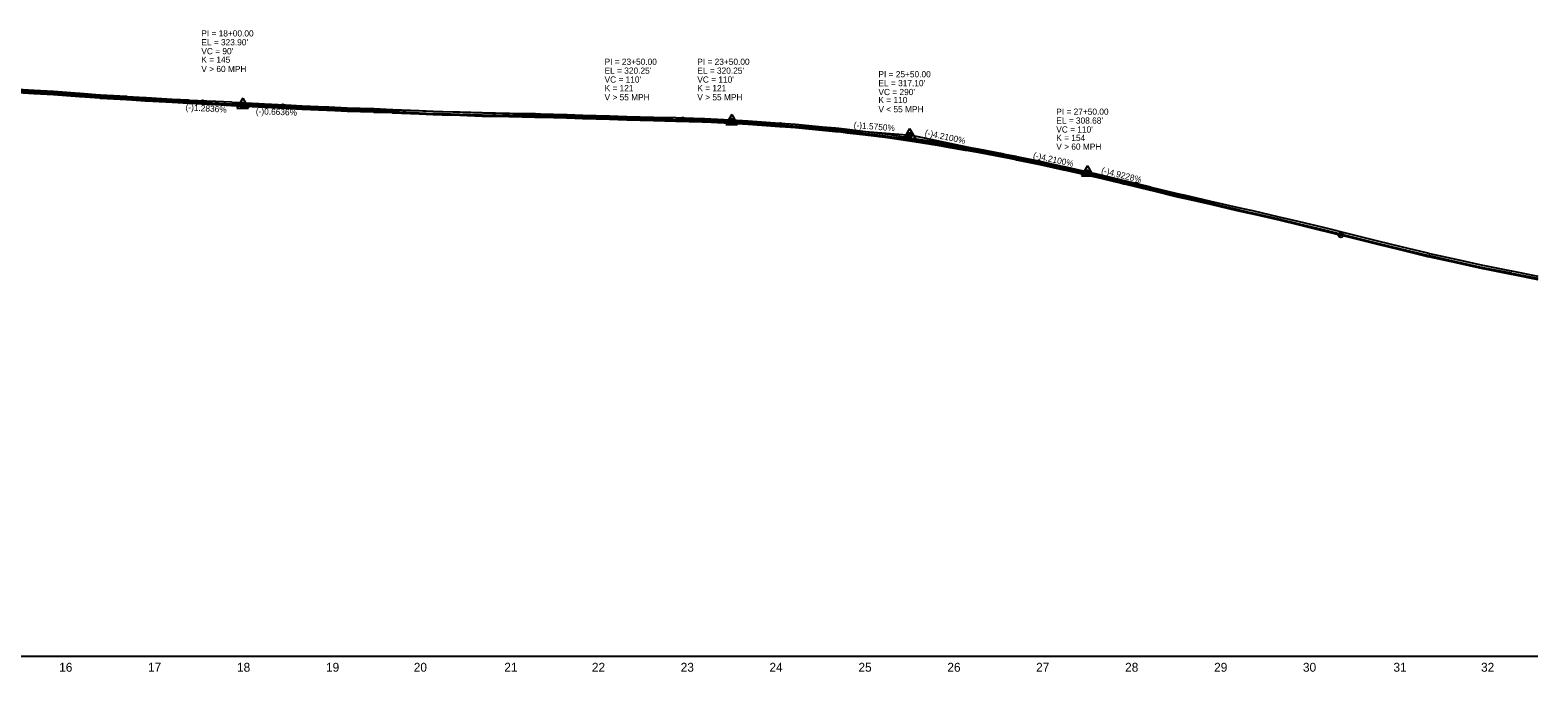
# Model space of a CAD drawing. Extents: x 2111382 to 2119088, y 667477 to 672158.
# Drawn here: x 2113288 to 2114983, y 670803 to 671524 of the extents above; entities that cross this region are included whole.
import ezdxf

# ---------------------------------------------------------------- set-up
doc = ezdxf.new("R2010")
doc.units = 0
for name, color, linetype in [('Exist Profile Cell', 7, 'Continuous'), ('Exist Vertical Profile Ground Line', 7, 'Continuous'), ('Exist Vertical Profile Horizontal Axis Label Major', 7, 'Continuous'), ('Prop PFL VPI Symbol CELL', 7, 'Continuous'), ('Prop Vertical Profile Curve Label', 7, 'Continuous'), ('Prop Vertical Profile Grade', 7, 'Continuous'), ('Prop Vertical Profile Grade Label', 7, 'Continuous'), ('Prop VPI Label', 7, 'Continuous'), ('Scratch_Level_2', 7, 'Continuous'), ('Scratch_Level_3', 7, 'Continuous')]:
    doc.layers.add(name, color=color, linetype=linetype)

msp = doc.modelspace()

# ---------------------------------------------------------------- linework, layer by layer
at = {"layer": 'Exist Profile Cell'}
msp.add_line((2112726.7, 670820.2), (2114983.3, 670820.2), dxfattribs=at)
at = {"layer": 'Exist Vertical Profile Ground Line'}
for points in [[(2113262.2, 671454.5), (2113291.9, 671452.7), (2113292.3, 671452.6), (2113313.9, 671451.3), (2113343.1, 671449.2), (2113343.9, 671449.1), (2113366.1, 671447.5), (2113366.7, 671447.4), (2113395.9, 671445.6), (2113396.7, 671445.6), (2113417, 671444.3), (2113417.5, 671444.3), (2113418.2, 671444.3), (2113447.5, 671442.6), (2113466.1, 671441.5), (2113466.7, 671441.5), (2113495.9, 671440.1), (2113496.7, 671440), (2113514.2, 671439.2), (2113514.6, 671439.2), (2113544.7, 671437.6), (2113551.1, 671437.3), (2113574.5, 671436), (2113574.8, 671436), (2113593.6, 671435), (2113621.3, 671433.9), (2113623.6, 671433.8), (2113644.3, 671432.8), (2113673.8, 671431.8), (2113674.3, 671431.7), (2113674.7, 671431.7), (2113695, 671431), (2113695.5, 671430.9), (2113725.2, 671429.6), (2113740.8, 671428.9), (2113751, 671428.6), (2113770.8, 671428), (2113771.1, 671428), (2113796.1, 671427.2), (2113826.1, 671426.7), (2113826.6, 671426.7), (2113855.3, 671426.1), (2113856.2, 671426.1), (2113861.6, 671426), (2113891, 671425.1), (2113891.6, 671425.1), (2113908.9, 671424.6), (2113909.3, 671424.6), (2113939.2, 671423.6), (2113958.6, 671423), (2113988.6, 671422.2), (2114013.8, 671421.6), (2114043.4, 671420.8), (2114043.9, 671420.8), (2114045.5, 671420.7), (2114046, 671420.7), (2114075.5, 671419.1), (2114075.8, 671419.1), (2114095.3, 671418), (2114125.4, 671415.8), (2114148.4, 671414.2), (2114178.3, 671411.4), (2114193.4, 671410), (2114197.3, 671409.7), (2114206.7, 671408.5), (2114227.3, 671406), (2114251.8, 671403), (2114282, 671398.4), (2114309.9, 671394.1), (2114310.3, 671394), (2114317.8, 671392.7), (2114339.4, 671389), (2114340.3, 671388.8), (2114353.3, 671386.5), (2114382.6, 671380.9), (2114383.2, 671380.8), (2114396.4, 671378.2), (2114397, 671378.1), (2114423.2, 671372.6), (2114450, 671366.7), (2114450.4, 671366.6), (2114480.1, 671360.1), (2114485, 671358.9), (2114485.6, 671358.7), (2114515, 671351.7), (2114517.6, 671351.1), (2114518.3, 671350.9), (2114547.6, 671343.8), (2114548.1, 671343.7), (2114577.5, 671336.5), (2114584.8, 671334.9), (2114585.1, 671334.8), (2114615, 671328), (2114644.8, 671321.1), (2114658.6, 671318), (2114662.2, 671317.2), (2114692.1, 671310.4), (2114713.2, 671305.3), (2114743.3, 671298.2)], [(2114743.3, 671298.2), (2114773, 671290.6), (2114802.9, 671283.1), (2114829.3, 671276.7), (2114859.3, 671269.5), (2114861.3, 671269.1), (2114891.2, 671262.5), (2114921.2, 671255.9), (2114923.4, 671255.4), (2114953.3, 671249.5), (2114953.7, 671249.5), (2114983.3, 671243.6)]]:
    msp.add_lwpolyline(points, dxfattribs=at)
at = {"layer": 'Prop PFL VPI Symbol CELL'}
for p, q in [((2113526.7, 671447.2), (2113520.2, 671436)), ((2113526.7, 671447.2), (2113533.2, 671436)), ((2113520.2, 671436), (2113533.2, 671436)), ((2114076.7, 671429), (2114070.2, 671417.8)), ((2114076.7, 671429), (2114083.2, 671417.8)), ((2114070.2, 671417.8), (2114083.2, 671417.8)), ((2114276.7, 671413.2), (2114270.2, 671402)), ((2114276.7, 671413.2), (2114283.2, 671402)), ((2114270.2, 671402), (2114283.2, 671402)), ((2114476.7, 671371.1), (2114470.2, 671359.9)), ((2114476.7, 671371.1), (2114483.2, 671359.9)), ((2114470.2, 671359.9), (2114483.2, 671359.9))]:
    msp.add_line(p, q, dxfattribs=at)
for centre, radius in [((2113526.7, 671439.7), 1.75), ((2113526.7, 671439.7), 1.2), ((2114076.7, 671421.5), 1.75), ((2114076.7, 671421.5), 1.2), ((2114276.7, 671405.7), 1.75), ((2114276.7, 671405.7), 1.2), ((2114476.7, 671363.6), 1.75), ((2114476.7, 671363.6), 1.2)]:
    msp.add_circle(centre, radius, dxfattribs=at)
at = {"layer": 'Prop Vertical Profile Curve Label'}
for centre in [(2113481.7, 671442.6), (2113571.7, 671438.2), (2114021.7, 671423.3), (2114131.7, 671417.2), (2114131.7, 671417.2), (2114421.7, 671375.2), (2114421.7, 671375.2), (2114531.7, 671350.1)]:
    msp.add_circle(centre, 2.25, dxfattribs=at)
at = {"layer": 'Prop Vertical Profile Grade'}
for p, q in [((2112986.7, 671474.4), (2113481.7, 671442.6)), ((2113571.7, 671438.2), (2114021.7, 671423.3)), ((2114531.7, 671350.1), (2114761.7, 671293.5))]:
    msp.add_line(p, q, dxfattribs=at)
for points in [[(2113481.7, 671442.6), (2113483.5, 671442.5), (2113485.3, 671442.4), (2113487.1, 671442.3), (2113488.9, 671442.2), (2113490.7, 671442.1), (2113492.5, 671441.9), (2113494.3, 671441.8), (2113496.1, 671441.7), (2113497.9, 671441.6), (2113499.7, 671441.5), (2113501.5, 671441.4), (2113503.3, 671441.3), (2113505.1, 671441.2), (2113506.9, 671441.1), (2113508.7, 671441), (2113510.5, 671440.9), (2113512.3, 671440.8), (2113514.1, 671440.7), (2113515.9, 671440.6), (2113517.7, 671440.5), (2113519.5, 671440.4), (2113521.3, 671440.4), (2113523.1, 671440.3), (2113524.9, 671440.2), (2113526.7, 671440.1), (2113528.5, 671440), (2113530.3, 671439.9), (2113532.1, 671439.8), (2113533.9, 671439.7), (2113535.7, 671439.7), (2113537.5, 671439.6), (2113539.3, 671439.5), (2113541.1, 671439.4), (2113542.9, 671439.3), (2113544.7, 671439.3), (2113546.5, 671439.2), (2113548.3, 671439.1), (2113550.1, 671439), (2113551.9, 671439), (2113553.7, 671438.9), (2113555.5, 671438.8), (2113557.3, 671438.8), (2113559.1, 671438.7), (2113560.9, 671438.6), (2113562.7, 671438.6), (2113564.5, 671438.5), (2113566.3, 671438.4), (2113568.1, 671438.4), (2113569.9, 671438.3), (2113571.7, 671438.2)], [(2114021.7, 671423.3), (2114023.9, 671423.2), (2114026.1, 671423.2), (2114028.3, 671423.1), (2114030.5, 671423), (2114032.7, 671422.9), (2114034.9, 671422.8), (2114037.1, 671422.7), (2114039.3, 671422.7), (2114041.5, 671422.6), (2114043.7, 671422.5), (2114045.9, 671422.4), (2114048.1, 671422.3), (2114050.3, 671422.2), (2114052.5, 671422.1), (2114054.7, 671422), (2114056.9, 671421.9), (2114059.1, 671421.8), (2114061.3, 671421.7), (2114063.5, 671421.6), (2114065.7, 671421.4), (2114067.9, 671421.3), (2114070.1, 671421.2), (2114072.3, 671421.1), (2114074.5, 671421), (2114076.7, 671420.9), (2114078.9, 671420.7), (2114081.1, 671420.6), (2114083.3, 671420.5), (2114085.5, 671420.3), (2114087.7, 671420.2), (2114089.9, 671420.1), (2114092.1, 671419.9), (2114094.3, 671419.8), (2114096.5, 671419.7), (2114098.7, 671419.5), (2114100.9, 671419.4), (2114103.1, 671419.2), (2114105.3, 671419.1), (2114107.5, 671418.9), (2114109.7, 671418.8), (2114111.9, 671418.6), (2114114.1, 671418.5), (2114116.3, 671418.3), (2114118.5, 671418.2), (2114120.7, 671418), (2114122.9, 671417.8), (2114125.1, 671417.7), (2114127.3, 671417.5), (2114129.5, 671417.3), (2114131.7, 671417.2)], [(2114131.7, 671417.2), (2114137.5, 671416.7), (2114143.3, 671416.2), (2114149.1, 671415.7), (2114154.9, 671415.2), (2114160.7, 671414.7), (2114166.5, 671414.1), (2114172.3, 671413.6), (2114178.1, 671413), (2114183.9, 671412.4), (2114189.7, 671411.8), (2114195.5, 671411.2), (2114201.3, 671410.6), (2114207.1, 671409.9), (2114212.9, 671409.3), (2114218.7, 671408.6), (2114224.5, 671407.9), (2114230.3, 671407.2), (2114236.1, 671406.5), (2114241.9, 671405.7), (2114247.7, 671405), (2114253.5, 671404.2), (2114259.3, 671403.4), (2114265.1, 671402.6), (2114270.9, 671401.8), (2114276.7, 671401), (2114282.5, 671400.1), (2114288.3, 671399.2), (2114294.1, 671398.4), (2114299.9, 671397.5), (2114305.7, 671396.6), (2114311.5, 671395.6), (2114317.3, 671394.7), (2114323.1, 671393.8), (2114328.9, 671392.8), (2114334.7, 671391.8), (2114340.5, 671390.8), (2114346.3, 671389.8), (2114352.1, 671388.8), (2114357.9, 671387.7), (2114363.7, 671386.7), (2114369.5, 671385.6), (2114375.3, 671384.5), (2114381.1, 671383.4), (2114386.9, 671382.3), (2114392.7, 671381.1), (2114398.5, 671380), (2114404.3, 671378.8), (2114410.1, 671377.6), (2114415.9, 671376.4), (2114421.7, 671375.2)], [(2114421.7, 671375.2), (2114423.9, 671374.7), (2114426.1, 671374.3), (2114428.3, 671373.8), (2114430.5, 671373.3), (2114432.7, 671372.9), (2114434.9, 671372.4), (2114437.1, 671371.9), (2114439.3, 671371.5), (2114441.5, 671371), (2114443.7, 671370.5), (2114445.9, 671370), (2114448.1, 671369.5), (2114450.3, 671369.1), (2114452.5, 671368.6), (2114454.7, 671368.1), (2114456.9, 671367.6), (2114459.1, 671367.1), (2114461.3, 671366.6), (2114463.5, 671366.1), (2114465.7, 671365.6), (2114467.9, 671365.1), (2114470.1, 671364.6), (2114472.3, 671364.1), (2114474.5, 671363.6), (2114476.7, 671363.1), (2114478.9, 671362.6), (2114481.1, 671362.1), (2114483.3, 671361.6), (2114485.5, 671361.1), (2114487.7, 671360.6), (2114489.9, 671360.1), (2114492.1, 671359.6), (2114494.3, 671359.1), (2114496.5, 671358.6), (2114498.7, 671358), (2114500.9, 671357.5), (2114503.1, 671357), (2114505.3, 671356.5), (2114507.5, 671356), (2114509.7, 671355.4), (2114511.9, 671354.9), (2114514.1, 671354.4), (2114516.3, 671353.8), (2114518.5, 671353.3), (2114520.7, 671352.8), (2114522.9, 671352.2), (2114525.1, 671351.7), (2114527.3, 671351.2), (2114529.5, 671350.6), (2114531.7, 671350.1)]]:
    msp.add_spline(points, degree=3, dxfattribs=at)
at = {"layer": 'Prop VPI Label'}
for p, q in [((2113481.7, 671442.6), (2113523.9, 671439.9)), ((2113571.7, 671438.2), (2113529.4, 671439.6)), ((2114021.7, 671423.3), (2114073.9, 671421.6)), ((2114131.7, 671417.2), (2114079.4, 671421.3)), ((2114131.7, 671417.2), (2114273.9, 671405.9)), ((2114421.7, 671375.2), (2114279.4, 671405.2)), ((2114421.7, 671375.2), (2114474, 671364.2)), ((2114531.7, 671350.1), (2114479.3, 671363))]:
    msp.add_line(p, q, dxfattribs=at)
for centre in [(2113526.7, 671439.7), (2113526.7, 671439.7), (2114076.7, 671421.5), (2114276.7, 671405.7), (2114476.7, 671363.6), (2114761.7, 671293.5)]:
    msp.add_circle(centre, 2.75, dxfattribs=at)
at = {"layer": 'Scratch_Level_2'}
for points in [[(2113262.2, 671455.7), (2113291.9, 671453.9), (2113292.3, 671453.9), (2113313.9, 671452.6), (2113343.1, 671450.4), (2113343.9, 671450.4), (2113366.1, 671448.7), (2113366.7, 671448.7), (2113395.9, 671446.9), (2113396.7, 671446.8), (2113417, 671445.6), (2113417.5, 671445.5), (2113418.2, 671445.5), (2113447.5, 671443.8), (2113466.1, 671442.8), (2113466.7, 671442.7), (2113495.9, 671441.3), (2113496.7, 671441.3), (2113514.2, 671440.5), (2113514.6, 671440.4), (2113544.7, 671438.9), (2113551.1, 671438.5), (2113574.5, 671437.3), (2113574.8, 671437.3), (2113593.6, 671436.3), (2113621.3, 671435.1), (2113623.6, 671435), (2113644.3, 671434.1), (2113673.8, 671433), (2113674.3, 671433), (2113674.7, 671433), (2113695, 671432.2), (2113695.5, 671432.2), (2113725.2, 671430.9), (2113740.8, 671430.2), (2113751, 671429.9), (2113770.8, 671429.3), (2113771.1, 671429.3), (2113796.1, 671428.5), (2113826.1, 671427.9), (2113826.6, 671427.9), (2113855.3, 671427.4), (2113856.2, 671427.4), (2113861.6, 671427.2), (2113891, 671426.4), (2113891.6, 671426.3), (2113908.9, 671425.8), (2113909.3, 671425.8), (2113939.2, 671424.9), (2113958.6, 671424.2), (2113988.6, 671423.5), (2114013.8, 671422.9), (2114043.4, 671422), (2114043.9, 671422), (2114045.5, 671422), (2114046, 671421.9), (2114075.5, 671420.3), (2114075.8, 671420.3), (2114095.3, 671419.3), (2114125.4, 671417.1), (2114148.4, 671415.4), (2114178.3, 671412.7), (2114193.4, 671411.3), (2114197.3, 671410.9), (2114206.7, 671409.8), (2114227.3, 671407.3), (2114251.8, 671404.3), (2114282, 671399.6), (2114309.9, 671395.3), (2114310.3, 671395.3), (2114317.8, 671394), (2114339.4, 671390.2), (2114340.3, 671390.1), (2114353.3, 671387.8), (2114382.6, 671382.1), (2114383.2, 671382), (2114396.4, 671379.5), (2114397, 671379.3), (2114423.2, 671373.8), (2114450, 671367.9), (2114450.4, 671367.8), (2114480.1, 671361.3), (2114485, 671360.1), (2114485.6, 671360), (2114515, 671353), (2114517.6, 671352.4), (2114518.3, 671352.2), (2114547.6, 671345.1), (2114548.1, 671344.9), (2114577.5, 671337.8), (2114584.8, 671336.1), (2114585.1, 671336.1), (2114615, 671329.2), (2114644.8, 671322.4), (2114658.6, 671319.3), (2114662.2, 671318.5), (2114692.1, 671311.6), (2114713.2, 671306.6), (2114743.3, 671299.4)], [(2114743.3, 671299.4), (2114773, 671291.9), (2114802.9, 671284.3), (2114829.3, 671278), (2114859.3, 671270.8), (2114861.3, 671270.3), (2114891.2, 671263.7), (2114921.2, 671257.1), (2114923.4, 671256.7), (2114953.3, 671250.8), (2114953.7, 671250.7), (2114983.3, 671244.9)]]:
    msp.add_lwpolyline(points, dxfattribs=at)
at = {"layer": 'Scratch_Level_3'}
for points in [[(2113262.2, 671458.2), (2113291.9, 671456.4), (2113292.3, 671456.4), (2113313.9, 671455.1), (2113343.1, 671452.9), (2113343.9, 671452.9), (2113366.1, 671451.2), (2113366.7, 671451.2), (2113395.9, 671449.4), (2113396.7, 671449.3), (2113417, 671448.1), (2113417.5, 671448), (2113418.2, 671448), (2113447.5, 671446.3), (2113466.1, 671445.3), (2113466.7, 671445.2), (2113495.9, 671443.8), (2113496.7, 671443.8), (2113514.2, 671443), (2113514.6, 671442.9), (2113544.7, 671441.4), (2113551.1, 671441), (2113574.5, 671439.8), (2113574.8, 671439.8), (2113593.6, 671438.8), (2113621.3, 671437.6), (2113623.6, 671437.5), (2113644.3, 671436.6), (2113673.8, 671435.5), (2113674.3, 671435.5), (2113674.7, 671435.5), (2113695, 671434.7), (2113695.5, 671434.7), (2113725.2, 671433.4), (2113740.8, 671432.7), (2113751, 671432.4), (2113770.8, 671431.8), (2113771.1, 671431.8), (2113796.1, 671431), (2113826.1, 671430.4), (2113826.6, 671430.4), (2113855.3, 671429.9), (2113856.2, 671429.9), (2113861.6, 671429.7), (2113891, 671428.9), (2113891.6, 671428.8), (2113908.9, 671428.3), (2113909.3, 671428.3), (2113939.2, 671427.4), (2113958.6, 671426.7), (2113988.6, 671426), (2114013.8, 671425.4), (2114043.4, 671424.5), (2114043.9, 671424.5), (2114045.5, 671424.5), (2114046, 671424.4), (2114075.5, 671422.8), (2114075.8, 671422.8), (2114095.3, 671421.8), (2114125.4, 671419.6), (2114148.4, 671417.9), (2114178.3, 671415.2), (2114193.4, 671413.8), (2114197.3, 671413.4), (2114206.7, 671412.3), (2114227.3, 671409.8), (2114251.8, 671406.8), (2114282, 671402.1), (2114309.9, 671397.8), (2114310.3, 671397.8), (2114317.8, 671396.5), (2114339.4, 671392.7), (2114340.3, 671392.6), (2114353.3, 671390.3), (2114382.6, 671384.6), (2114383.2, 671384.5), (2114396.4, 671382), (2114397, 671381.8), (2114423.2, 671376.3), (2114450, 671370.4), (2114450.4, 671370.3), (2114480.1, 671363.8), (2114485, 671362.6), (2114485.6, 671362.5), (2114515, 671355.5), (2114517.6, 671354.9), (2114518.3, 671354.7), (2114547.6, 671347.6), (2114548.1, 671347.4), (2114577.5, 671340.3), (2114584.8, 671338.6), (2114585.1, 671338.6), (2114615, 671331.7), (2114644.8, 671324.9), (2114658.6, 671321.8), (2114662.2, 671321), (2114692.1, 671314.1), (2114713.2, 671309.1), (2114743.3, 671301.9)], [(2114743.3, 671301.9), (2114773, 671294.4), (2114802.9, 671286.8), (2114829.3, 671280.5), (2114859.3, 671273.3), (2114861.3, 671272.8), (2114891.2, 671266.2), (2114921.2, 671259.6), (2114923.4, 671259.2), (2114953.3, 671253.3), (2114953.7, 671253.2), (2114983.3, 671247.4)]]:
    msp.add_lwpolyline(points, dxfattribs=at)

# ---------------------------------------------------------------- texts
at = {"layer": 'Exist Vertical Profile Horizontal Axis Label Major'}
for s, p in [('16', (2113320.3, 670802.7)), ('17', (2113420.2, 670802.7)), ('18', (2113520.3, 670802.7)), ('19', (2113620.4, 670802.7)), ('20', (2113719.1, 670802.7)), ('21', (2113820.9, 670802.7)), ('22', (2113919.4, 670802.7)), ('23', (2114019.3, 670802.7)), ('24', (2114119.1, 670802.7)), ('25', (2114219.2, 670802.7)), ('26', (2114319.2, 670802.7)), ('27', (2114419, 670802.7)), ('28', (2114519.1, 670802.7)), ('29', (2114619.2, 670802.7)), ('30', (2114719.1, 670802.7)), ('31', (2114820.9, 670802.7)), ('32', (2114919.4, 670802.7))]:
    msp.add_text(s, height=10, dxfattribs=at).set_placement(p)
at = {"layer": 'Prop Vertical Profile Curve Label'}
for s, p in [("VC = 90'", (2113480.2, 671496.6)), ('K = 145', (2113480.2, 671487.1)), ('V > 60 MPH', (2113480.2, 671476.6)), ("VC = 110'", (2113933.7, 671464.7)), ("VC = 110'", (2114038, 671464.7)), ('K = 121', (2113933.7, 671455.1)), ('K = 121', (2114038, 671455.1)), ("VC = 290'", (2114241.7, 671450.7)), ('V > 55 MPH', (2113933.7, 671444.8)), ('V > 55 MPH', (2114038, 671444.8)), ('V < 55 MPH', (2114241.7, 671431.3)), ('K = 110', (2114241.7, 671441.7)), ("VC = 110'", (2114441.7, 671408.6)), ('K = 154', (2114441.7, 671399.2)), ('V > 60 MPH', (2114441.7, 671389.3))]:
    msp.add_text(s, height=7, dxfattribs=at).set_placement(p)
at = {"layer": 'Prop Vertical Profile Grade Label'}
for s, rotation, p in [('(-)1.2836%', 356.3278, (2113462.3, 671433.8)), ('(-)0.6636%', 358.0995, (2113541.4, 671429.2)), ('(-)1.5750%', 355.4973, (2114213.7, 671413.7)), ('(-)4.2100%', 348.1128, (2114293.4, 671405.3)), ('(-)4.2100%', 348.1128, (2114415.1, 671379.7)), ('(-)4.9228%', 346.1721, (2114491.8, 671363))]:
    msp.add_text(s, height=7, rotation=rotation, dxfattribs=at).set_placement(p)
at = {"layer": 'Prop VPI Label'}
for s, p in [('PI = 18+00.00', (2113480.2, 671516.6)), ("EL = 323.90'", (2113480.2, 671506.6)), ('PI = 23+50.00', (2113933.7, 671484.7)), ('PI = 23+50.00', (2114038, 671484.7)), ("EL = 320.25'", (2113933.7, 671474.7)), ("EL = 320.25'", (2114038, 671474.7)), ('PI = 25+50.00', (2114241.7, 671470.7)), ("EL = 317.10'", (2114241.7, 671460.7)), ('PI = 27+50.00', (2114441.7, 671428.6)), ("EL = 308.68'", (2114441.7, 671418.6))]:
    msp.add_text(s, height=7, dxfattribs=at).set_placement(p)

doc.saveas('drawing.dxf')
